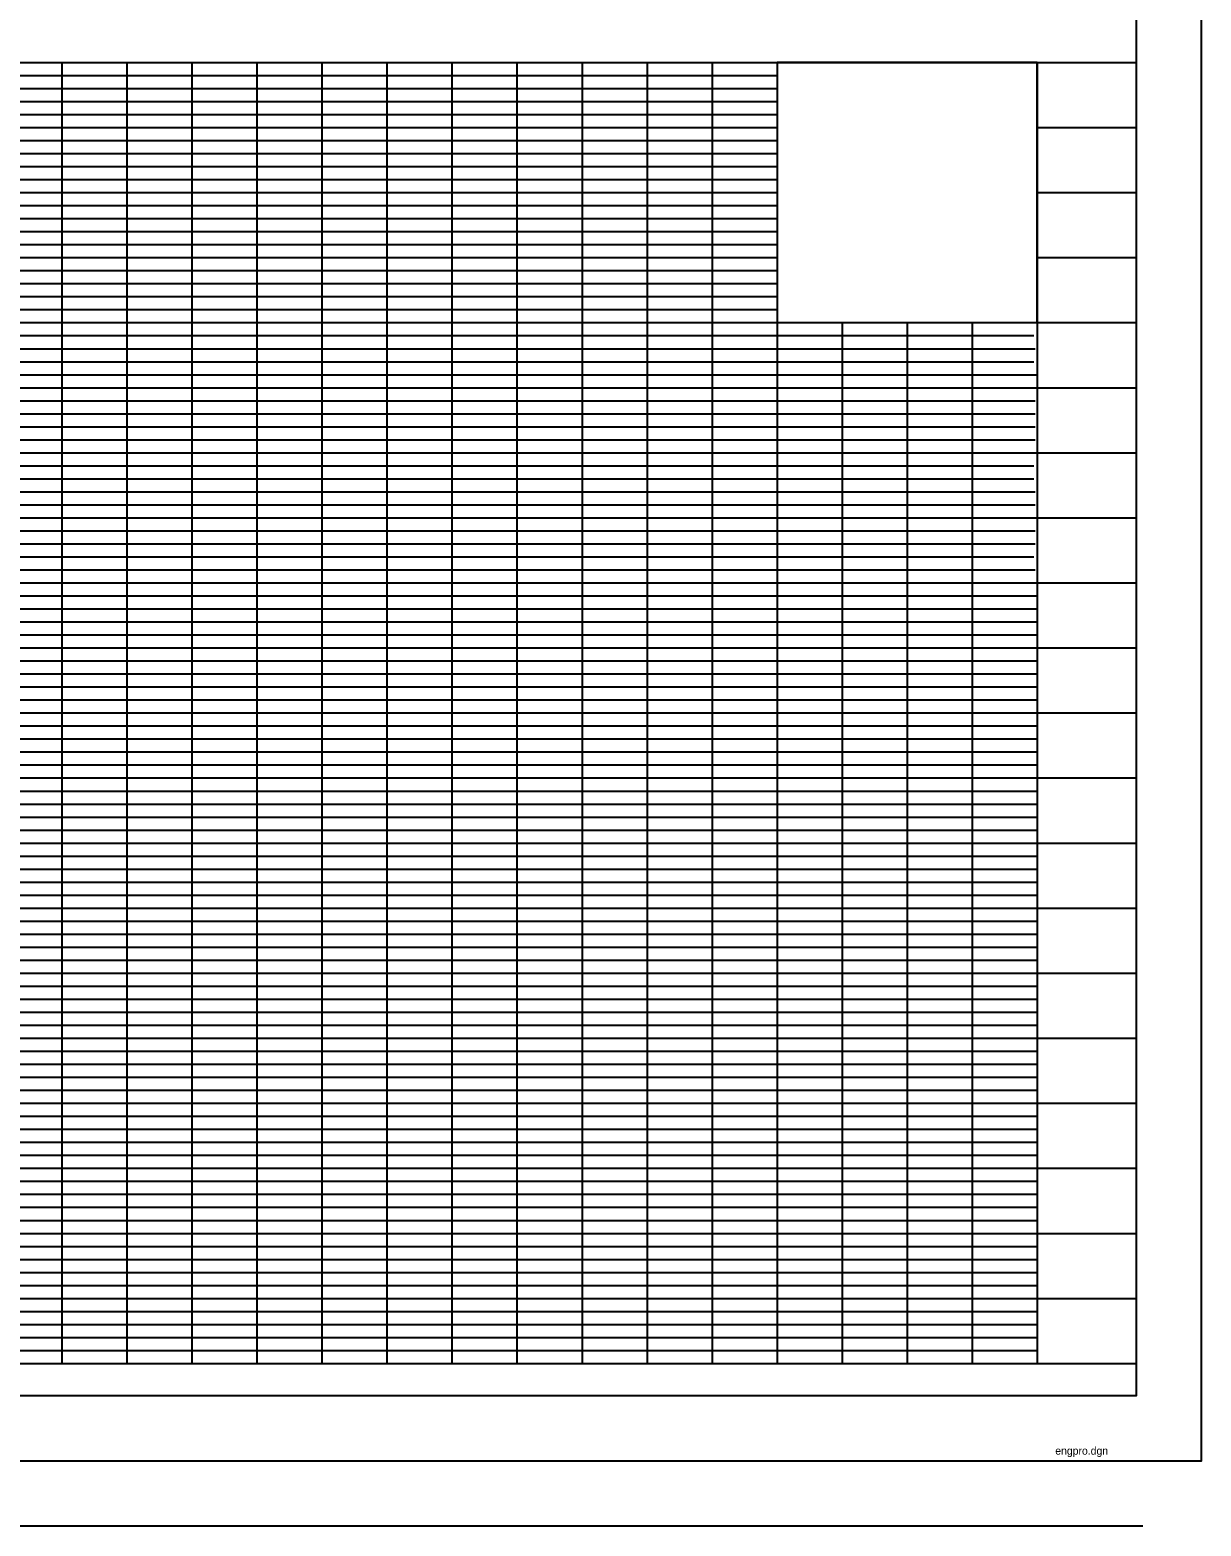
# Model space of a CAD drawing. Extents: x -183 to 1613, y -563 to 588.
# Drawn here: x 1163 to 1613, y -563 to 12 of the extents above; entities that cross this region are included whole.
import ezdxf

# ---------------------------------------------------------------- set-up
doc = ezdxf.new("R2010")
doc.units = 0
for name, color, linetype in [('RD_SHT_Bndy', 7, 'Continuous'), ('RD_SHT_IplotShp', 7, 'Continuous'), ('RD_SHT_MjGrid', 7, 'Continuous'), ('RD_SHT_MnGrid', 7, 'Continuous'), ('RD_SHT_SubGrid', 7, 'Continuous'), ('RD_SHT_TX', 7, 'Continuous')]:
    doc.layers.add(name, color=color, linetype=linetype)

msp = doc.modelspace()

# ---------------------------------------------------------------- linework, layer by layer
at = {"layer": 'RD_SHT_Bndy'}
for p, q in [((-87, 0), (1588, 0)), ((1550, 0), (1550, -500)), ((-87, -500), (1588, -500)), ((1590.65, -537.5), (-169.35, -537.5)), ((1590.65, -562.5), (-169.35, -562.5))]:
    msp.add_line(p, q, dxfattribs=at)
for points in [[(-87, 537.5), (1588, 537.5), (1588, -512.5), (-87, -512.5)], [(1550, 0), (1450, 0), (1450, -100), (1550, -100)]]:
    msp.add_lwpolyline(points, close=True, dxfattribs=at)
at = {"layer": 'RD_SHT_IplotShp'}
msp.add_lwpolyline([(-182.9, 562.5), (1613, 562.5), (1613, -537.5), (-182.9, -537.5)], close=True, dxfattribs=at)
at = {"layer": 'RD_SHT_MjGrid'}
for p, q in [((1200, 0), (1200, -500)), ((1250, 0), (1250, -500)), ((1300, 0), (1300, -500)), ((1350, 0), (1350, -500)), ((1400, 0), (1400, -500)), ((1450, 0), (1450, -500)), ((750, -50), (1450, -50)), ((1550, -50), (1588, -50)), ((-87, -100), (1588, -100)), ((1500, -100), (1500, -500)), ((-87, -150), (1588, -150)), ((-87, -200), (1588, -200)), ((-87, -250), (1588, -250)), ((-87, -300), (1588, -300)), ((-87, -350), (1588, -350)), ((-87, -400), (1588, -400)), ((-87, -450), (1588, -450))]:
    msp.add_line(p, q, dxfattribs=at)
at = {"layer": 'RD_SHT_MnGrid'}
for p, q in [((1175, 0), (1175, -500)), ((1225, 0), (1225, -500)), ((1275, 0), (1275, -500)), ((1325, 0), (1325, -500)), ((1375, 0), (1375, -500)), ((1425, 0), (1425, -500)), ((750, -25), (1450, -25)), ((1550, -25), (1588, -25)), ((750, -75), (1450, -75)), ((1550, -75), (1588, -75)), ((1475, -100), (1475, -500)), ((1525, -100), (1525, -500)), ((-87, -125), (1588, -125)), ((-87, -175), (1588, -175)), ((-87, -225), (1588, -225)), ((-87, -275), (1588, -275)), ((-87, -325), (1588, -325)), ((-87, -375), (1588, -375)), ((-87, -425), (1588, -425)), ((-87, -475), (1588, -475))]:
    msp.add_line(p, q, dxfattribs=at)
at = {"layer": 'RD_SHT_SubGrid'}
for p, q in [((750, -5), (1450, -5)), ((750, -10), (1450, -10)), ((750, -15), (1450, -15)), ((750, -20), (1450, -20)), ((750, -30), (1450, -30)), ((750, -35), (1450, -35)), ((750, -40), (1450, -40)), ((750, -45), (1450, -45)), ((750, -55), (1450, -55)), ((750, -60), (1450, -60)), ((750, -65), (1450, -65)), ((750, -70), (1450, -70)), ((750, -80), (1450, -80)), ((750, -85), (1450, -85)), ((750, -90), (1450, -90)), ((750, -95), (1450, -95)), ((-49.95, -105), (1548.75, -105)), ((-49.95, -110), (1549.25, -110)), ((-49.95, -115), (1548.75, -115)), ((-49.9, -120), (1549.8, -120)), ((-49.95, -130), (1549.25, -130)), ((-49.95, -135), (1549.25, -135)), ((-49.95, -140), (1549.25, -140)), ((-49.95, -145), (1549.25, -145)), ((-49.85, -155), (1548.75, -155)), ((-49.85, -160), (1548.75, -160)), ((-49.9, -165), (1549.25, -165)), ((-49.9, -170), (1549.25, -170)), ((-49.95, -180), (1549.25, -180)), ((-49.95, -185), (1549.25, -185)), ((-49.95, -190), (1548.75, -190)), ((-49.95, -195), (1549.25, -195)), ((-49.95, -195), (1549.25, -195)), ((-49.95, -205), (1549.8, -205)), ((-49.95, -210), (1549.8, -210)), ((-49.95, -215), (1549.8, -215)), ((-49.95, -220), (1549.8, -220)), ((-49.95, -230), (1549.8, -230)), ((-49.95, -235), (1549.8, -235)), ((-49.95, -240), (1549.8, -240)), ((-49.95, -245), (1549.8, -245)), ((-49.95, -255), (1549.85, -255)), ((-49.95, -260), (1549.85, -260)), ((-49.95, -265), (1549.85, -265)), ((-49.95, -270), (1549.85, -270)), ((-49.95, -280), (1549.85, -280)), ((-49.95, -285), (1549.85, -285)), ((-49.95, -290), (1549.85, -290)), ((-49.95, -295), (1549.85, -295)), ((-49.95, -305), (1549.85, -305)), ((-49.95, -310), (1549.85, -310)), ((-49.95, -315), (1549.85, -315)), ((-49.95, -320), (1549.85, -320)), ((-49.95, -330), (1549.85, -330)), ((-49.9, -330), (1549.85, -330)), ((-49.95, -335), (1549.85, -335)), ((-49.9, -340), (1549.6, -340)), ((-49.9, -345), (1549.6, -345)), ((-49.9, -355), (1549.8, -355)), ((-49.95, -360), (1549.95, -360)), ((-49.95, -365), (1549.95, -365)), ((-49.9, -370), (1549.95, -370)), ((-49.95, -380), (1549.95, -380)), ((-49.95, -385), (1549.95, -385)), ((-49.95, -390), (1549.95, -390)), ((-49.9, -395), (1549.95, -395)), ((-49.95, -405), (1549.95, -405)), ((-49.95, -410), (1549.95, -410)), ((-49.95, -415), (1549.95, -415)), ((-49.95, -420), (1549.85, -420)), ((-49.9, -430), (1549.6, -430)), ((-49.95, -435), (1549.85, -435)), ((-49.95, -440), (1549.85, -440)), ((-49.95, -445), (1549.85, -445)), ((-49.95, -460), (1549.85, -460)), ((-49.85, -455), (1549.85, -455)), ((-49.95, -465), (1549.85, -465)), ((-49.95, -470), (1549.85, -470)), ((-49.85, -480), (1549.85, -480)), ((-49.85, -485), (1549.85, -485)), ((-49.85, -490), (1549.85, -490)), ((-49.85, -495), (1549.85, -495))]:
    msp.add_line(p, q, dxfattribs=at)

# ---------------------------------------------------------------- texts
at = {"layer": 'RD_SHT_TX'}
msp.add_text('engpro.dgn', height=3, dxfattribs=at).set_placement((1556.95, -535.05))

doc.saveas('drawing.dxf')
